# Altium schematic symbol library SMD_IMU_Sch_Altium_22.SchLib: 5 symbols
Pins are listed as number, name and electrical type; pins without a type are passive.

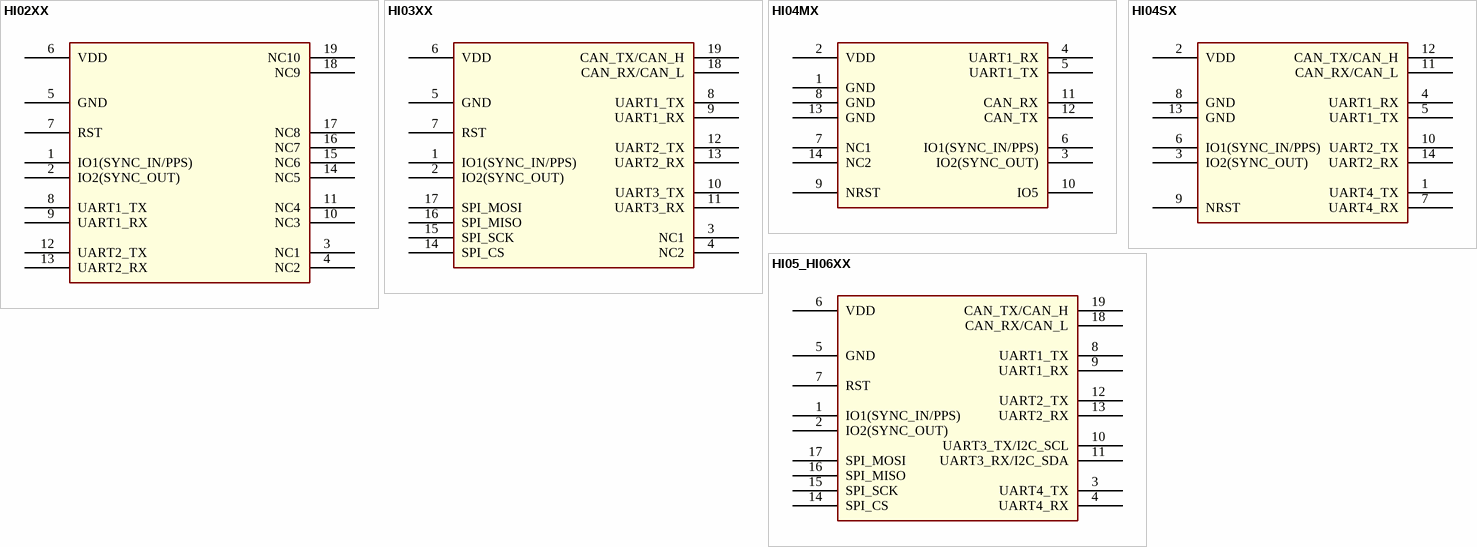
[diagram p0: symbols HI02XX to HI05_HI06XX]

## HI02XX
designator U?
pins: 1 IO1(SYNC_IN/PPS), 2 IO2(SYNC_OUT), 3 NC1, 4 NC2, 5 GND, 6 VDD, 7 RST, 8 UART1_TX, 9 UART1_RX, 10 NC3, 11 NC4, 12 UART2_TX, 13 UART2_RX, 14 NC5, 15 NC6, 16 NC7, 17 NC8 (power), 18 NC9 (power), 19 NC10 (power)

## HI03XX
designator U?
pins: 1 IO1(SYNC_IN/PPS), 2 IO2(SYNC_OUT), 3 NC1, 4 NC2, 5 GND, 6 VDD, 7 RST, 8 UART1_TX, 9 UART1_RX, 10 UART3_TX, 11 UART3_RX, 12 UART2_TX, 13 UART2_RX, 14 SPI_CS, 15 SPI_SCK, 16 SPI_MISO, 17 SPI_MOSI (power), 18 CAN_RX/CAN_L (power), 19 CAN_TX/CAN_H (power)

## HI04MX
designator U?
pins: 1 GND, 2 VDD, 3 IO2(SYNC_OUT), 4 UART1_RX, 5 UART1_TX, 6 IO1(SYNC_IN/PPS), 7 NC1, 8 GND, 9 NRST, 10 IO5, 11 CAN_RX, 12 CAN_TX, 13 GND, 14 NC2

## HI04SX
designator U?
pins: 1 UART4_TX, 2 VDD, 3 IO2(SYNC_OUT), 4 UART1_RX, 5 UART1_TX, 6 IO1(SYNC_IN/PPS), 7 UART4_RX, 8 GND, 9 NRST, 10 UART2_TX, 11 CAN_RX/CAN_L, 12 CAN_TX/CAN_H, 13 GND, 14 UART2_RX

## HI05_HI06XX
designator U?
pins: 1 IO1(SYNC_IN/PPS), 2 IO2(SYNC_OUT), 3 UART4_TX, 4 UART4_RX, 5 GND, 6 VDD, 7 RST, 8 UART1_TX, 9 UART1_RX, 10 UART3_TX/I2C_SCL, 11 UART3_RX/I2C_SDA, 12 UART2_TX, 13 UART2_RX, 14 SPI_CS, 15 SPI_SCK, 16 SPI_MISO, 17 SPI_MOSI (power), 18 CAN_RX/CAN_L (power), 19 CAN_TX/CAN_H (power)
